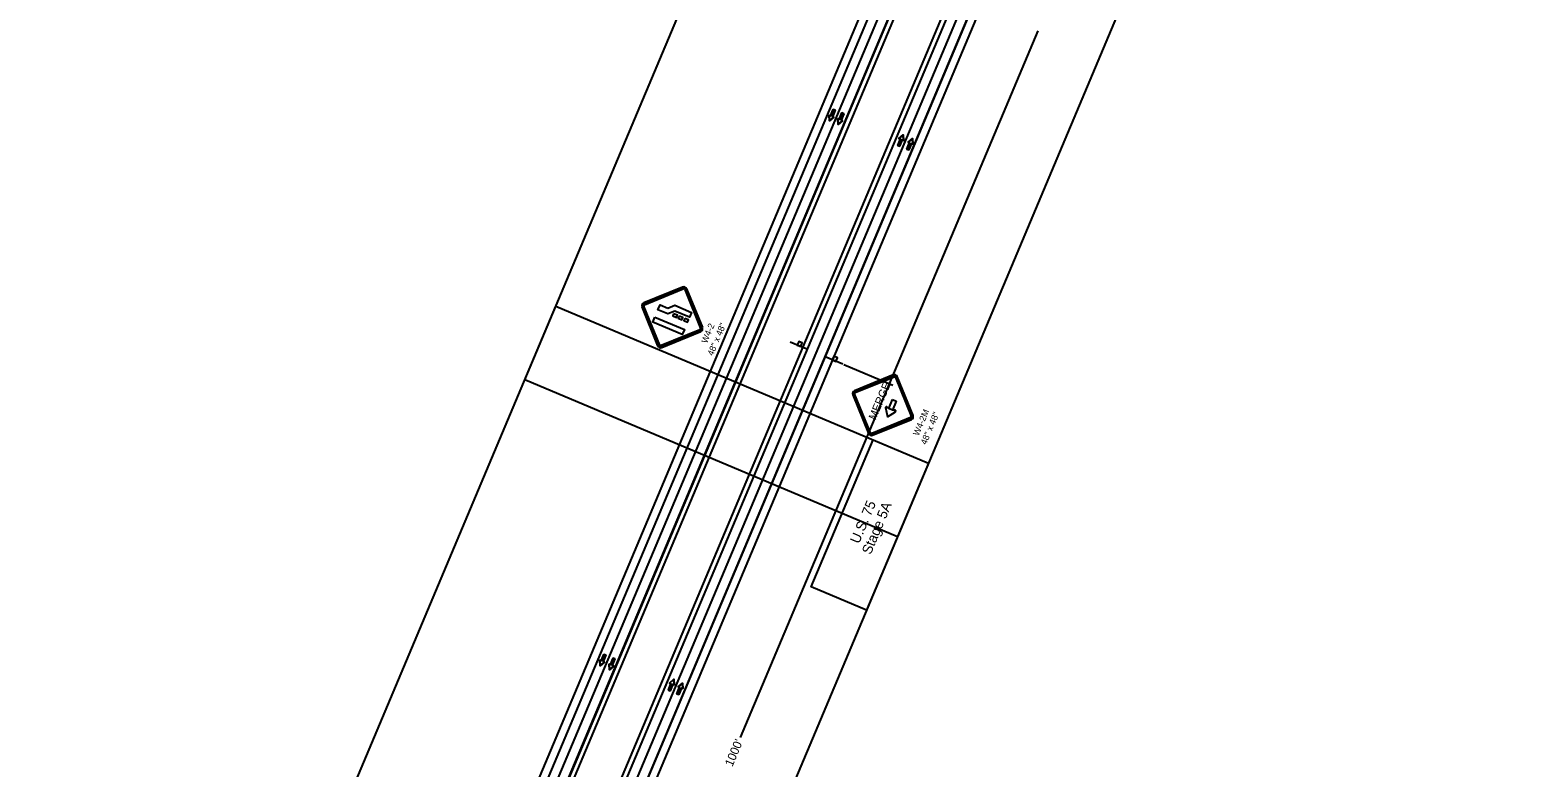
# Model space of a CAD drawing. Extents: x 14104283 to 14129344, y 8637090 to 8673339.
# Drawn here: x 14116868 to 14118725, y 8665326 to 8666247 of the extents above; entities that cross this region are included whole.
import ezdxf

# ---------------------------------------------------------------- set-up
doc = ezdxf.new("R2010")
doc.units = 0
for name, color, linetype in [('Cell', 7, 'Continuous'), ('Default', 7, 'Continuous'), ('dsnNonPlotable', 7, 'Continuous'), ('dsnPaintExistingBrokenLaneLineWhite', 7, 'Continuous'), ('dsnPaintExistingEdgeLineLeftYellow', 7, 'Continuous'), ('dsnPaintExistingEdgeLineRightWhite', 7, 'Continuous'), ('dsnShadingPaved', 7, 'Continuous'), ('dsnStdLabel', 7, 'Continuous'), ('dsnStgShadingPrevPav', 7, 'Continuous'), ('dsnTextOverlapEven', 7, 'Continuous')]:
    doc.layers.add(name, color=color, linetype=linetype)

msp = doc.modelspace()

# ---------------------------------------------------------------- linework, layer by layer
at = {"layer": 'Cell'}
for p, q in [((14117683.8, 8665925.4), (14117635.2, 8665905.6)), ((14117635.2, 8665905.6), (14117683.8, 8665925.4)), ((14117684.2, 8665924.6), (14117635.5, 8665904.8)), ((14117636.1, 8665903.3), (14117684.7, 8665923.1)), ((14117686.4, 8665922.4), (14117706.2, 8665873.8)), ((14117707.6, 8665874.4), (14117687.8, 8665923)), ((14117708.5, 8665874.8), (14117688.7, 8665923.4)), ((14117688.7, 8665923.4), (14117708.5, 8665874.8)), ((14117633.1, 8665900.8), (14117652.9, 8665852.1)), ((14117652.9, 8665852.1), (14117633.1, 8665900.8)), ((14117634, 8665901.1), (14117653.8, 8665852.5)), ((14117635.2, 8665905.6), (14117635.2, 8665905.6)), ((14117655.2, 8665853.1), (14117635.4, 8665901.7)), ((14117636.1, 8665903.3), (14117636.1, 8665903.3)), ((14117705.5, 8665872.2), (14117656.9, 8665852.4)), ((14117657.4, 8665850.9), (14117706.1, 8665870.7)), ((14117657.8, 8665850.1), (14117706.4, 8665869.9)), ((14117706.4, 8665869.9), (14117657.8, 8665850.1)), ((14117840.1, 8665847.4), (14117818, 8665856.7)), ((14117883.8, 8665829), (14117861.7, 8665838.3)), ((14117947, 8665815.7), (14117898.4, 8665795.9)), ((14117947.4, 8665814.9), (14117947.9, 8665813.4)), ((14117949.6, 8665812.7), (14117951, 8665813.3)), ((14117971.7, 8665765.1), (14117951.9, 8665813.7)), ((14117896.3, 8665791), (14117916.1, 8665742.4)), ((14117897.2, 8665791.4), (14117898.6, 8665792)), ((14117899.3, 8665793.6), (14117898.7, 8665795.1)), ((14117921, 8665740.4), (14117969.6, 8665760.2)), ((14117937.4, 8665774.9), (14117938.4, 8665775.1)), ((14117938.4, 8665775.1), (14117939, 8665775.9)), ((14117949.1, 8665771.6), (14117949, 8665770.6)), ((14117949, 8665770.6), (14117949.6, 8665769.8)), ((14117968.7, 8665762.5), (14117969.3, 8665761)), ((14117970.8, 8665764.7), (14117969.4, 8665764.1)), ((14117918.4, 8665743.4), (14117917, 8665742.8)), ((14117920.6, 8665741.2), (14117920.1, 8665742.7))]:
    msp.add_line(p, q, dxfattribs=at)
for points in [[(14117872, 8666147.3), (14117874.3, 8666146.3), (14117871, 8666138.2), (14117872.7, 8666137.5), (14117867.5, 8666132.9), (14117867, 8666139.9), (14117868.7, 8666139.2)], [(14117882.8, 8666143), (14117885.1, 8666142), (14117881.8, 8666133.9), (14117883.5, 8666133.2), (14117878.3, 8666128.6), (14117877.7, 8666135.6), (14117879.5, 8666134.9)], [(14117954.8, 8666101.3), (14117952.5, 8666102.3), (14117955.8, 8666110.4), (14117954.1, 8666111.1), (14117959.4, 8666115.7), (14117959.9, 8666108.7), (14117958.2, 8666109.4)], [(14117966.4, 8666096.7), (14117964.1, 8666097.7), (14117967.4, 8666105.8), (14117965.6, 8666106.5), (14117970.9, 8666111.1), (14117971.4, 8666104.1), (14117969.7, 8666104.8)], [(14117665.4, 8665899.3), (14117674.1, 8665902.8), (14117695.1, 8665893.9), (14117692.5, 8665887.7), (14117674.1, 8665895.5), (14117665.4, 8665891.9), (14117653, 8665897.1), (14117655.7, 8665903.4)], [(14117672.6, 8665892.1), (14117671.5, 8665889.4), (14117676.1, 8665887.4), (14117677.3, 8665890.2)], [(14117679.6, 8665889.2), (14117678.4, 8665886.5), (14117683, 8665884.5), (14117684.2, 8665887.3)], [(14117649.1, 8665887.8), (14117686, 8665872.3), (14117683.4, 8665866.1), (14117646.5, 8665881.6)], [(14117686.5, 8665886.3), (14117685.3, 8665883.6), (14117689.9, 8665881.6), (14117691.1, 8665884.4)], [(14117826.9, 8665853.1), (14117831.4, 8665851.1), (14117833.3, 8665855.7), (14117828.8, 8665857.6)], [(14117870.7, 8665834.6), (14117875.2, 8665832.7), (14117877.1, 8665837.2), (14117872.6, 8665839.1)], [(14117947.4, 8665814.9), (14117898.7, 8665795.1), (14117899.3, 8665793.6), (14117947.9, 8665813.4), (14117947.4, 8665814.9)], [(14117970.8, 8665764.7), (14117951, 8665813.3), (14117949.6, 8665812.7), (14117969.4, 8665764.1), (14117970.8, 8665764.7)], [(14117897.2, 8665791.4), (14117917, 8665742.8), (14117918.4, 8665743.4), (14117898.6, 8665792), (14117897.2, 8665791.4)], [(14117946.1, 8665785.1), (14117950.7, 8665783.1), (14117946, 8665771.9), (14117941.4, 8665773.8), (14117946.1, 8665785.1)], [(14117920.6, 8665741.2), (14117969.3, 8665761), (14117968.7, 8665762.5), (14117920.1, 8665742.7), (14117920.6, 8665741.2)], [(14117939.7, 8665763.5), (14117949.6, 8665769.8), (14117949, 8665770.6), (14117949.1, 8665771.6), (14117946, 8665771.9), (14117941.4, 8665773.8), (14117939, 8665775.9), (14117938.4, 8665775.1), (14117937.4, 8665774.9), (14117939.7, 8665763.5)], [(14117585.4, 8665466.8), (14117587.8, 8665465.8), (14117584.4, 8665457.8), (14117586.2, 8665457), (14117580.9, 8665452.4), (14117580.4, 8665459.4), (14117582.1, 8665458.7)], [(14117596.9, 8665461.9), (14117599.2, 8665461), (14117595.9, 8665452.9), (14117597.7, 8665452.2), (14117592.4, 8665447.6), (14117591.9, 8665454.6), (14117593.6, 8665453.9)], [(14117668.3, 8665421.3), (14117666, 8665422.2), (14117669.3, 8665430.3), (14117667.6, 8665431), (14117672.8, 8665435.6), (14117673.3, 8665428.6), (14117671.6, 8665429.4)], [(14117679.1, 8665416.6), (14117676.8, 8665417.6), (14117680.1, 8665425.7), (14117678.4, 8665426.4), (14117683.7, 8665431), (14117684.2, 8665424), (14117682.5, 8665424.7)]]:
    msp.add_lwpolyline(points, close=True, dxfattribs=at)
for points in [[(14117868.7, 8666139.2), (14117867, 8666139.9), (14117867.5, 8666132.9), (14117872.7, 8666137.5), (14117871, 8666138.2), (14117874.3, 8666146.3), (14117872, 8666147.3), (14117868.7, 8666139.2)], [(14117879.5, 8666134.9), (14117877.7, 8666135.6), (14117878.3, 8666128.6), (14117883.5, 8666133.2), (14117881.8, 8666133.9), (14117885.1, 8666142), (14117882.8, 8666143), (14117879.5, 8666134.9)], [(14117958.2, 8666109.4), (14117959.9, 8666108.7), (14117959.4, 8666115.7), (14117954.1, 8666111.1), (14117955.8, 8666110.4), (14117952.5, 8666102.3), (14117954.8, 8666101.3), (14117958.2, 8666109.4)], [(14117969.7, 8666104.8), (14117971.4, 8666104.1), (14117970.9, 8666111.1), (14117965.6, 8666106.5), (14117967.4, 8666105.8), (14117964.1, 8666097.7), (14117966.4, 8666096.7), (14117969.7, 8666104.8)], [(14117635.5, 8665904.8), (14117684.2, 8665924.6)], [(14117636.1, 8665903.3), (14117684.7, 8665923.1)], [(14117686.4, 8665922.4), (14117706.2, 8665873.8)], [(14117687.8, 8665923), (14117707.6, 8665874.4)], [(14117653.8, 8665852.5), (14117634, 8665901.1)], [(14117655.2, 8665853.1), (14117635.4, 8665901.7)], [(14117705.5, 8665872.2), (14117656.9, 8665852.4)], [(14117706.1, 8665870.7), (14117657.4, 8665850.9)], [(14117826.9, 8665853.1), (14117831.4, 8665851.1), (14117833.3, 8665855.7), (14117828.8, 8665857.6), (14117826.9, 8665853.1)], [(14117870.7, 8665834.6), (14117875.2, 8665832.7), (14117877.1, 8665837.2), (14117872.6, 8665839.1), (14117870.7, 8665834.6)], [(14117582.1, 8665458.7), (14117580.4, 8665459.4), (14117580.9, 8665452.4), (14117586.2, 8665457), (14117584.4, 8665457.8), (14117587.8, 8665465.8), (14117585.4, 8665466.8), (14117582.1, 8665458.7)], [(14117593.6, 8665453.9), (14117591.9, 8665454.6), (14117592.4, 8665447.6), (14117597.7, 8665452.2), (14117595.9, 8665452.9), (14117599.2, 8665461), (14117596.9, 8665461.9), (14117593.6, 8665453.9)], [(14117671.6, 8665429.4), (14117673.3, 8665428.6), (14117672.8, 8665435.6), (14117667.6, 8665431), (14117669.3, 8665430.3), (14117666, 8665422.2), (14117668.3, 8665421.3), (14117671.6, 8665429.4)], [(14117682.5, 8665424.7), (14117684.2, 8665424), (14117683.7, 8665431), (14117678.4, 8665426.4), (14117680.1, 8665425.7), (14117676.8, 8665417.6), (14117679.1, 8665416.6), (14117682.5, 8665424.7)]]:
    msp.add_lwpolyline(points, dxfattribs=at)
for centre, radius, start, end in [((14117685.2, 8665922), 3.75, 22.1549, 112.1545), ((14117685.2, 8665922), 3.75, 22.1549, 112.1545), ((14117685.2, 8665922), 2.81, 22.1549, 112.1545), ((14117685.2, 8665922), 2.81, 22.1549, 112.1545), ((14117685.2, 8665922), 1.25, 22.1549, 112.1545), ((14117685.2, 8665922), 1.25, 22.1549, 112.1545), ((14117636.6, 8665902.2), 3.75, 112.1547, 202.1544), ((14117636.6, 8665902.2), 3.75, 112.1547, 202.1544), ((14117636.6, 8665902.2), 2.81, 112.1547, 202.1544), ((14117636.6, 8665902.2), 2.81, 112.1547, 202.1544), ((14117636.6, 8665902.2), 1.25, 112.1547, 202.1544), ((14117636.6, 8665902.2), 1.25, 112.1547, 202.1544), ((14117705, 8665873.3), 1.25, 292.1547, 22.1549), ((14117705, 8665873.3), 1.25, 292.1547, 22.1549), ((14117705, 8665873.3), 2.81, 292.1547, 22.1549), ((14117705, 8665873.3), 2.81, 292.1547, 22.1549), ((14117705, 8665873.3), 3.75, 292.1547, 22.1549), ((14117705, 8665873.3), 3.75, 292.1547, 22.1549), ((14117656.4, 8665853.5), 3.75, 202.1544, 292.1547), ((14117656.4, 8665853.5), 3.75, 202.1544, 292.1547), ((14117656.4, 8665853.5), 2.81, 202.1544, 292.1547), ((14117656.4, 8665853.5), 2.81, 202.1544, 292.1547), ((14117656.4, 8665853.5), 1.25, 202.1544, 292.1547), ((14117656.4, 8665853.5), 1.25, 202.1544, 292.1547), ((14117948.4, 8665812.3), 3.75, 22.1549, 112.1545), ((14117948.4, 8665812.3), 2.81, 22.1549, 112.1545), ((14117899.8, 8665792.5), 3.75, 112.1547, 202.1544), ((14117948.4, 8665812.3), 1.25, 22.1549, 112.1545), ((14117899.8, 8665792.5), 2.81, 112.1547, 202.1544), ((14117899.8, 8665792.5), 1.25, 112.1547, 202.1544), ((14117938.4, 8665775.1), 1.02, 48.5734, 189.4671), ((14117949, 8665770.6), 1.02, 304.8422, 85.7366), ((14117968.2, 8665763.6), 1.25, 292.1547, 22.1549), ((14117968.2, 8665763.6), 2.81, 292.1547, 22.1549), ((14117968.2, 8665763.6), 3.75, 292.1547, 22.1549), ((14117919.6, 8665743.8), 3.75, 202.1544, 292.1547), ((14117919.6, 8665743.8), 2.81, 202.1544, 292.1547), ((14117919.6, 8665743.8), 1.25, 202.1544, 292.1547)]:
    msp.add_arc(centre, radius, start, end, dxfattribs=at)
at = {"layer": 'Default'}
for points in [[(14118413.2, 8667444.3), (14110818.4, 8649409.2), (14109142.6, 8645431.4)], [(14109164.7, 8645422.1), (14110840.5, 8649399.8), (14118435.4, 8667434.9)]]:
    msp.add_lwpolyline(points, dxfattribs=at)
at = {"layer": 'dsnNonPlotable'}
for points in [[(14117486.7, 8665809.5), (14118095.3, 8667254.1), (14118560.7, 8667058), (14117952.1, 8665613.5)], [(14116917, 8664457.1), (14117525.6, 8665901.7), (14117990.9, 8665705.6), (14117382.4, 8664261.1)]]:
    msp.add_lwpolyline(points, close=True, dxfattribs=at)
at = {"layer": 'dsnPaintExistingBrokenLaneLineWhite'}
for p, q in [((14114932.5, 8658913.4), (14118863.7, 8668248.6)), ((14110829.5, 8649404.5), (14118424.3, 8667439.6))]:
    msp.add_line(p, q, dxfattribs=at)
at = {"layer": 'dsnPaintExistingEdgeLineLeftYellow'}
for p, q in [((14115900.9, 8661244), (14118759.4, 8668031.7)), ((14118435.4, 8667434.9), (14115816.1, 8661215.2)), ((14118435.4, 8667434.9), (14115816.1, 8661215.2))]:
    msp.add_line(p, q, dxfattribs=at)
at = {"layer": 'dsnPaintExistingEdgeLineRightWhite'}
for p, q in [((14110924.4, 8649364.5), (14118874.7, 8668243.7)), ((14118413.2, 8667444.3), (14115798.8, 8661235.7))]:
    msp.add_line(p, q, dxfattribs=at)
at = {"layer": 'dsnShadingPaved'}
for p, q in [((14115901.2, 8661244.5), (14118227.7, 8666769.2)), ((14118249.8, 8666759.9), (14115923.3, 8661235.2))]:
    msp.add_line(p, q, dxfattribs=at)
at = {"layer": 'dsnStdLabel'}
for p, q in [((14118127.5, 8666245.3), (14117941.9, 8665804.6)), ((14117946.5, 8665802.6), (14117885.2, 8665828.4)), ((14117941.9, 8665804.6), (14117755.9, 8665363.1))]:
    msp.add_line(p, q, dxfattribs=at)
at = {"layer": 'dsnStgShadingPrevPav'}
for p, q in [((14115895.6, 8661246.8), (14118811.5, 8668171)), ((14118848.4, 8668155.5), (14115932.5, 8661231.3)), ((14118653, 8668013.6), (14115794, 8661224.5)), ((14115816.1, 8661215.2), (14118675.1, 8668004.3)), ((14115816.1, 8661215.2), (14118675.1, 8668004.3)), ((14118680.7, 8668002), (14115821.7, 8661212.9)), ((14110809.2, 8649413), (14118404, 8667448.1)), ((14118413.2, 8667444.3), (14110818.4, 8649409.2))]:
    msp.add_line(p, q, dxfattribs=at)
at = {"layer": 'dsnTextOverlapEven'}
for points in [[(14117990.9, 8665705.6), (14117913.6, 8665522), (14117844.5, 8665551.1), (14117921.8, 8665734.7)], [(14117844.5, 8665551.1), (14117921.8, 8665734.7), (14117990.9, 8665705.6), (14117913.6, 8665522)]]:
    msp.add_lwpolyline(points, close=True, dxfattribs=at)

# ---------------------------------------------------------------- texts
at = {"layer": 'Cell'}
for s, height, p in [('W4-2', 8, (14117714.1, 8665854.5)), ('48" x 48"', 8, (14117721.7, 8665839)), ('MERGE', 10, (14117924.9, 8665758.7)), ('W4-2M', 8, (14117978.7, 8665739)), ('48" x 48"', 8, (14117988.1, 8665727.9))]:
    msp.add_text(s, height=height, rotation=67.1547, dxfattribs=at).set_placement(p)
at = {"layer": 'dsnStdLabel'}
msp.add_text("1000'", height=10.8, rotation=67.1547, dxfattribs=at).set_placement((14117746, 8665325.8))
at = {"layer": 'dsnTextOverlapEven'}
for s, p in [('U.S. 75', (14117904.1, 8665604.1)), ('Stage 5A', (14117918.7, 8665590.5))]:
    msp.add_text(s, height=12.5, rotation=67.1547, dxfattribs=at).set_placement(p)

doc.saveas('drawing.dxf')
